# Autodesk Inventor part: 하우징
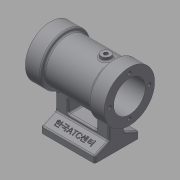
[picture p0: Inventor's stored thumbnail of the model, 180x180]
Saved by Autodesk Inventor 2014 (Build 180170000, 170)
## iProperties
Created: 2018-01
Part Number: 하우징
Material: 알루미늄 6061
Document SubType Name: Modeling
Designer: mduedu
Density: 1 g/cm^3
Appearance: 기본값
Author: mduedu
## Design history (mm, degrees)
sketch "스케치1"
  geometry: L1 (-25, 0)-(25, 0); L2 (-25, 0)-(-25, 16); L3 (-25, 16)-(-15, 16); L4 (-15, 16)-(-15, 14); L5 (-15, 14)-(15, 14); L6 (15, 14)-(15, 16); L7 (15, 16)-(25, 16); L8 (25, 16)-(25, 0); 2 further points
  constraints: 16 end point, 3 parallel, 2 collinear, 2 perpendicular, 1 coincident, 1 horizontal, 1 midpoint, 1 vertical
  dimensions: "d0" = 50 distance of L1.start L1.end; "d2" = 10 distance of L2.end L3.end; "d3" = 10 distance of L6.end L7.end (= d2); "d4" = 32 diameter of L3 L1; "d5" = 28 diameter of L5 L1
revolve "회전1" sketch "스케치1" stored, may be unused: angle "d6" = 90 deg
hole "구멍1" diameter "d9" = 20; stored, may be unused: countersink angle "d13" = 90 deg, drill point angle "d15" = 118 deg; dims "d7" = 10, "d8" = 10, "d10" = 6, "d11" = 4, "d12" = 2, "d14" = 8
fillet "모깎기1" dims "d16" = 1
sketch "스케치2"
  geometry: L1 (0, 0)-(-34, 0); L2 (-34, 14)-(-34, -14); L3 (-34, 14)-(-30, 14); L4 (-30, 14)-(-26, 5); L5 (-26, 5)-(-13.077, 5); L6 (-26, -5)-(-13.077, -5); L7 (-30, -14)-(-26, -5); L8 (-34, -14)-(-30, -14); C1 r 10 at (0, 0) reference; A1 r 14 centre (0, 0) between (-13.077, 5) and (-13.077, -5); 2 further points
  constraints: 16 end point, 3 symmetric about line, 2 perpendicular, 2 point on circle, 1 centre point, 1 coincident, 1 horizontal, 1 midpoint, 1 parallel, 2 other
  dimensions: "d17" = 34 distance of L1.end L1.start; "d18" = 28 distance between parallel lines of L8 L3; "d19" = 10 distance between parallel lines of L6 L5; "d20" = 4 distance of L2.end L7.start; "d21" = 8 distance from line of L6.start L2
extrude "돌출1" join sketch "스케치2" stored distance "d22" = 34; taper "d23" = 0 deg
sketch "스케치3"
  geometry: L1 (-9, -16)-(9, -16); L2 (9, -16)-(9, -24); L3 (9, -24)-(-9, -24); L4 (-9, -24)-(-9, -16); L5 (-17, -15.199)-(-17, -26) reference; L6 (17, -26)-(17, -15.199) reference; L7 (-17, -34)-(17, -34) reference; 1 further point
  constraints: 8 end point, 2 parallel, 1 horizontal, 1 perpendicular
  dimensions: "d24" = 8 distance between parallel lines of L4 L5; "d25" = 8 distance between parallel lines of L2 L6; "d26" = 10 distance between parallel lines of L3 L7; "d27" = 8 distance of L1.end L2.end
extrude "돌출2" cut sketch "스케치3" stored distance "d28" = 34; taper "d29" = 0 deg
fillet "모깎기2" dims "d30" = 1
fillet "모깎기3" dims "d31" = 1
fillet "모깎기4" dims "d32" = 1
fillet "모깎기5" dims "d33" = 1
fillet "모깎기6" dims "d34" = 1
sketch "스케치4"
  geometry: 4 further points
  constraints: 4 other
hole "구멍2" sketch "스케치4" at (-12.5, 0), (0, -12.5), (12.5, 0), (0, 12.5) diameter "d35" = 2.459; stored, may be unused: countersink angle "d39" = 90 deg, drill point angle "d41" = 120 deg; dims "d36" = 5.5, "d37" = 4, "d38" = 2, "d40" = 7
sketch "스케치5"
  geometry: 4 further points
  constraints: 4 other
hole "구멍4" sketch "스케치5" at (-12.5, 0), (0, -12.5), (12.5, 0), (0, 12.5) diameter "d42" = 2.459; stored, may be unused: countersink angle "d46" = 90 deg, drill point angle "d48" = 120 deg; dims "d43" = 5.5, "d44" = 4, "d45" = 2, "d47" = 7
sketch "스케치6"
  geometry: 2 further points
  constraints: 2 other
hole "구멍5" sketch "스케치6" at (7, 14), (25, 14) diameter "d49" = 2.459; stored, may be unused: countersink angle "d53" = 90 deg, drill point angle "d55" = 120 deg; dims "d50" = 6.9, "d51" = 4, "d52" = 2, "d54" = 8.4
node "작업 평면1"
sketch "스케치7"
  geometry: L1 (-25, 16)-(-25, -16) reference; C1 r 3 at (-10, 0); 1 further point
  constraints: 1 centre point, 1 horizontal alignment
  dimensions: "d57" = 6 diameter of C1; "d60" = 15 distance from line of C1.centre L1
extrude "돌출3" join sketch "스케치7" stored distance "d61" = 10; taper "d62" = 0 deg
fillet "모깎기7" dims "d63" = 1
hole "구멍6" diameter "d66" = 2.459; stored, may be unused: countersink angle "d70" = 90 deg, drill point angle "d72" = 118 deg; dims "d64" = 10, "d65" = 10, "d67" = 6, "d68" = 4, "d69" = 2, "d71" = 8
sketch "스케치8"
  geometry: L1 (-1, 0)-(0, 0) reference; L2 (0, 0)-(0, 8.549) reference; L3 (0, 8.549)-(-1, 8.549) reference; L4 (-1, 8.549)-(-1, 0) reference; L5 (32, 0)-(33, 0) reference; L6 (33, 0)-(33, 8.549) reference; L7 (32, 8.549)-(33, 8.549) reference; L8 (32, 8.549)-(32, 0) reference; 3 further points
  constraints: 1 horizontal alignment, 1 midpoint, 1 vertical alignment, 1 other
feature "엠보싱1" sketch "스케치8" dims "d73" = 0.5, "d74" = 0
node "솔리드1"
node "투영된 루프1"
node "투영된 루프2"
node "절단 모서리 투영1"
other parameters: "d56" = 16
